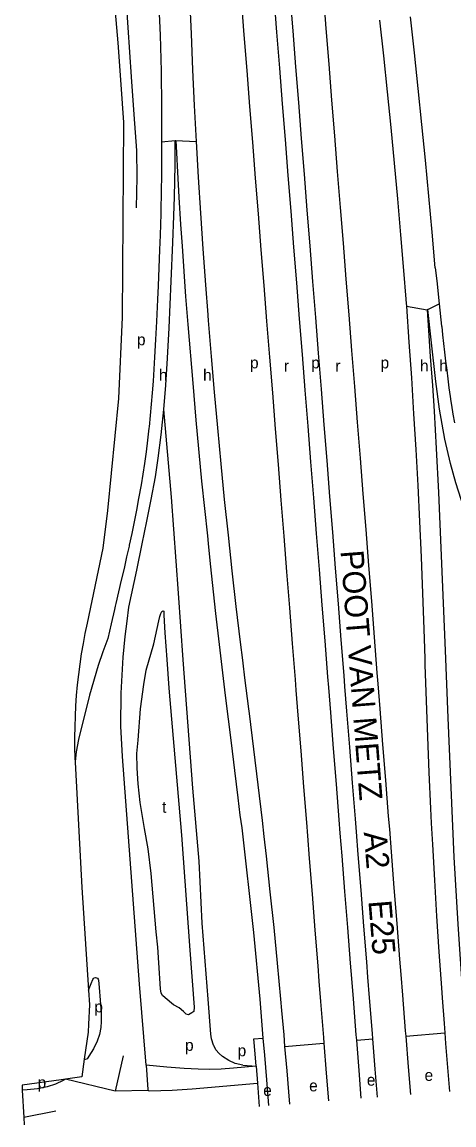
# Model space of a CAD drawing. Extents: x 157794 to 159375, y 380877 to 382306.
# Drawn here: x 157793.8 to 157944, y 380877 to 381260.8 of the extents above; entities that cross this region are included whole.
import ezdxf

# ---------------------------------------------------------------- set-up
doc = ezdxf.new("R2010")
doc.units = 0
for name, color, linetype in [('BLT_Basislijn', 7, 'Continuous'), ('BLT_Centroide', 7, 'Continuous'), ('BLT_Gemeentegrens', 7, 'Continuous'), ('BLT_Straatnaam_hoofdweg', 7, 'Continuous'), ('BLT_Vlakafsluiter', 7, 'Continuous')]:
    doc.layers.add(name, color=color, linetype=linetype)

msp = doc.modelspace()

# ---------------------------------------------------------------- linework, layer by layer
at = {"layer": 'BLT_Basislijn'}
for p, q in [((157847.06, 381219.6), (157847.27, 381219.6)), ((157845.78, 381095.42), (157843.13, 381125.9)), ((157910.17, 380906.42), (157915.75, 380906.88)), ((157927.21, 380907.85), (157940.76, 380908.99)), ((157885.1, 380904.31), (157898.71, 380905.45)), ((157828.9, 380900.99), (157826.11, 380888.76)), ((157870.61, 380897.76), (157875.17, 380897.39)), ((157875.17, 380897.39), (157875.62, 380891.48)), ((157875.62, 380891.48), (157876.23, 380883.41)), ((157805.55, 380881.8), (157794.37, 380879.52))]:
    msp.add_line(p, q, dxfattribs=at)
for points in [[(157838.3, 381404.1), (157838.34, 381403.5), (157838.4, 381401.23), (157838.41, 381400.88), (157838.57, 381393.52), (157838.8, 381381.04), (157838.98, 381368.57), (157839.09, 381356.1), (157839.15, 381343.62), (157839.16, 381340.46), (157839.15, 381331.16), (157839.14, 381328.66), (157839.56, 381318.71), (157840.04, 381306.27), (157840.46, 381293.82), (157840.62, 381288.51), (157840.84, 381281.32), (157840.89, 381279.75), (157841.27, 381268.78), (157841.76, 381256.24), (157842.11, 381243.7), (157842.3, 381231.14), (157842.32, 381219.08)], [(157825.06, 381390.44), (157823.42, 381383.18), (157823.24, 381377.09), (157823.39, 381366.32), (157823.39, 381358.68), (157823.61, 381346.59), (157824.14, 381335.97), (157824.42, 381322.97), (157825.55, 381312.41), (157827.15, 381295.92), (157829.34, 381277.88), (157830.56, 381258.85), (157831.69, 381241.7), (157832.65, 381228.56), (157833.59, 381216.13), (157833.7, 381206.77), (157833.46, 381196.16)], [(157851.57, 381283.73), (157851.63, 381281.67), (157851.68, 381280.1), (157852.06, 381269.18), (157852.55, 381256.69), (157853.09, 381244.2), (157853.69, 381231.72), (157854.35, 381219.24)], [(157898.49, 381271.05), (157899.47, 381258.59), (157900.46, 381246.13), (157901.44, 381233.66), (157902.43, 381221.2), (157903.41, 381208.74), (157904.4, 381196.28), (157905.39, 381183.82), (157906.37, 381171.36), (157907.36, 381158.9), (157908.34, 381146.44), (157909.33, 381133.98), (157910.31, 381121.51), (157911.3, 381109.05), (157912.28, 381096.59), (157913.27, 381084.13), (157914.25, 381071.67), (157915.24, 381059.21), (157916.22, 381046.75), (157917.21, 381034.29), (157917.51, 381030.49), (157918.19, 381021.83), (157919.18, 381009.36), (157920.17, 380996.9), (157921.15, 380984.44), (157921.51, 380979.88), (157922.14, 380971.98), (157923.12, 380959.52), (157924.11, 380947.06), (157925.09, 380934.6), (157925.51, 380929.27), (157926.08, 380922.14), (157927.06, 380909.68), (157927.21, 380907.85)], [(157869.98, 381268.79), (157870.96, 381256.33), (157871.95, 381243.87), (157872.93, 381231.41), (157873.92, 381218.95), (157874.9, 381206.49), (157875.89, 381194.03), (157876.87, 381181.57), (157877.86, 381169.1), (157878.84, 381156.64), (157879.83, 381144.18), (157880.82, 381131.72), (157881.8, 381119.26), (157882.79, 381106.8), (157883.77, 381094.34), (157884.76, 381081.88), (157885.74, 381069.42), (157886.73, 381056.95), (157887.71, 381044.49), (157888.7, 381032.03), (157889, 381028.23), (157889.68, 381019.57), (157890.67, 381007.11), (157891.65, 380994.65), (157892.64, 380982.19), (157893, 380977.63), (157893.63, 380969.73), (157894.61, 380957.27), (157895.6, 380944.8), (157896.58, 380932.34), (157897, 380927.02), (157897.57, 380919.88), (157898.55, 380907.42), (157898.71, 380905.45)], [(157910.17, 380906.42), (157910.02, 380908.33), (157909.03, 380920.79), (157908.47, 380927.92), (157908.05, 380933.25), (157907.06, 380945.71), (157906.07, 380958.17), (157905.09, 380970.63), (157904.46, 380978.53), (157904.1, 380983.09), (157903.12, 380995.56), (157902.13, 381008.02), (157901.15, 381020.48), (157900.46, 381029.14), (157900.16, 381032.94), (157899.18, 381045.4), (157898.19, 381057.86), (157897.21, 381070.32), (157896.22, 381082.78), (157895.24, 381095.24), (157894.25, 381107.71), (157893.27, 381120.17), (157892.28, 381132.63), (157891.29, 381145.09), (157890.31, 381157.55), (157889.32, 381170.01), (157888.34, 381182.47), (157887.35, 381194.93), (157886.37, 381207.39), (157885.38, 381219.86), (157884.4, 381232.32), (157883.41, 381244.78), (157882.43, 381257.24), (157881.44, 381269.7)], [(157915.75, 380906.88), (157915.6, 380908.77), (157914.61, 380921.23), (157914.05, 380928.37), (157913.63, 380933.69), (157912.64, 380946.15), (157911.66, 380958.61), (157910.67, 380971.07), (157910.05, 380978.97), (157909.69, 380983.54), (157908.7, 380996), (157907.72, 381008.46), (157906.73, 381020.92), (157906.05, 381029.58), (157905.75, 381033.38), (157904.76, 381045.84), (157903.77, 381058.3), (157902.79, 381070.76), (157901.8, 381083.22), (157900.82, 381095.69), (157899.83, 381108.15), (157898.85, 381120.61), (157897.86, 381133.07), (157896.88, 381145.53), (157895.89, 381157.99), (157894.91, 381170.45), (157893.92, 381182.91), (157892.94, 381195.37), (157891.95, 381207.84), (157890.96, 381220.3), (157889.98, 381232.76), (157888.99, 381245.22), (157888.01, 381257.68), (157887.02, 381270.14)], [(157937.46, 381175.29), (157936.38, 381187.7), (157935.23, 381200.19), (157934.03, 381212.68), (157932.77, 381225.17), (157931.51, 381237.65), (157930.2, 381250.13), (157928.83, 381262.6)], [(157918.1, 381261.4), (157919.46, 381248.98), (157920.77, 381236.55), (157922.02, 381224.11), (157923.22, 381211.67), (157924.35, 381199.22), (157925.43, 381186.77), (157926.45, 381174.32), (157927.22, 381164.35), (157927.24, 381164.08), (157927.41, 381161.86)], [(157842.32, 381219.08), (157842.26, 381206.53), (157842.21, 381202.85), (157842.03, 381194.03)], [(157843.13, 381125.9), (157843.81, 381134.42), (157844.35, 381143.77), (157844.99, 381154.35), (157845.62, 381170.58), (157846.22, 381184.02), (157846.59, 381193.38), (157846.79, 381199.99), (157847, 381210.94), (157847.06, 381219.6)], [(157847.27, 381219.6), (157847.49, 381215.33), (157847.82, 381208.58), (157848.36, 381199.89), (157848.94, 381190.37), (157849.42, 381182.8), (157850.64, 381165.33), (157851.38, 381155.49), (157853.12, 381135.14), (157854.18, 381122.23), (157856.2, 381100.97), (157858.25, 381082.03), (157858.48, 381079.28), (157859.22, 381072.24), (157861.1, 381054.94), (157862.33, 381044.14), (157864.45, 381026.42), (157866.46, 381009.89), (157867.64, 381000.35), (157868.84, 380990.8), (157869.49, 380984.81), (157870.22, 380980.34), (157874.22, 380943.96), (157876.44, 380920.72), (157877.57, 380907.2)], [(157854.35, 381219.24), (157855.07, 381206.76), (157855.84, 381194.29), (157856.68, 381181.82), (157857.57, 381169.35), (157858.36, 381158.88), (157858.37, 381158.68), (157858.51, 381156.89), (157859.52, 381144.43), (157860.58, 381131.98), (157861.7, 381119.53), (157862.88, 381107.09), (157864.12, 381094.65), (157865.41, 381082.22), (157866.76, 381069.8), (157868.17, 381057.38), (157869.64, 381044.97), (157870.39, 381038.75)], [(157842.03, 381194.03), (157841.81, 381186.67), (157841.63, 381181.53), (157841.09, 381169.04), (157840.88, 381164.24), (157840.53, 381156.56), (157840.23, 381150.34), (157839.89, 381144.12), (157839.64, 381139.98), (157839.36, 381135.85), (157839.05, 381131.73), (157838.73, 381127.79), (157838.36, 381123.86), (157837.96, 381119.94), (157837.9, 381119.4), (157837.42, 381115.31), (157836.9, 381111.22), (157836.32, 381107.14), (157835.76, 381103.45), (157835.16, 381099.77), (157834.31, 381094.94), (157833.55, 381090.88), (157832.75, 381086.83), (157831.91, 381082.77), (157831.05, 381078.72), (157830.98, 381078.4), (157830.15, 381074.68), (157829.24, 381070.63), (157828.31, 381066.58), (157827.37, 381062.53), (157826.42, 381058.48), (157826.18, 381057.47), (157825.92, 381056.35), (157824.74, 381051.32), (157823.59, 381046.25), (157821.88, 381041.64), (157820.26, 381036.82), (157817.27, 381026.54), (157813.41, 381011.07), (157812.65, 381006.8), (157812.32, 381004.6), (157812.24, 381003.17)], [(157937.46, 381175.29), (157937.96, 381170.68), (157938.83, 381162.75)], [(157927.41, 381161.86), (157928.32, 381149.39), (157929.16, 381136.92), (157929.95, 381124.45), (157930.69, 381111.97), (157931.36, 381099.49), (157931.98, 381087.01), (157932.53, 381074.53), (157933.03, 381062.04), (157933.48, 381049.55), (157933.69, 381042.72), (157933.8, 381039.18), (157933.86, 381037.05), (157934.27, 381024.56), (157934.73, 381012.07), (157935.25, 380999.57), (157935.83, 380987.09), (157936.08, 380981.95), (157936.47, 380974.6), (157937.16, 380962.12), (157937.91, 380949.64), (157938.72, 380937.16), (157939.59, 380924.69), (157939.84, 380921.25), (157940.51, 380912.22), (157940.76, 380908.99)], [(157934.94, 381160.71), (157934.65, 381160.68)], [(157934.65, 381160.68), (157935.7, 381144.42), (157936.49, 381134.3), (157937.03, 381125.41), (157937.84, 381112.36), (157938.63, 381097.02), (157939.91, 381066.83), (157940.97, 381042.02), (157941.87, 381018.61), (157942.89, 380994.44), (157943.91, 380970.19), (157945.28, 380946.87), (157946.92, 380922.55), (157947.64, 380912.88)], [(157955.82, 381069.77), (157951.64, 381079.87), (157948.21, 381089.13), (157944.6, 381100.37), (157942.75, 381107.14), (157940.84, 381115.66), (157938.98, 381126.08), (157937.64, 381135.68), (157936.03, 381150.24), (157934.94, 381160.71)], [(157938.83, 381162.75), (157939.69, 381154.98), (157939.71, 381154.78), (157940.02, 381151.96), (157940.02, 381151.93), (157940.36, 381148.89), (157940.7, 381145.85), (157941.06, 381142.76), (157941.44, 381139.68), (157941.82, 381136.6), (157942.23, 381133.53), (157942.66, 381130.46), (157942.91, 381128.77), (157943.12, 381127.41), (157943.6, 381124.36), (157944.12, 381121.32)], [(157836.89, 380897.78), (157834.67, 380925.92), (157828.71, 381005.16), (157828.15, 381015.78), (157828.23, 381027.2), (157828.97, 381039.75), (157829.7, 381046.91), (157830.33, 381052.34), (157830.95, 381057.1), (157833.74, 381069.99), (157835.6, 381079.14), (157837.23, 381087.08), (157838.72, 381094.64), (157840.22, 381102.57), (157841.17, 381108.97), (157842.17, 381117.12), (157843.13, 381125.9)], [(157860.41, 380904.67), (157859.66, 380906.89), (157859.42, 380908.58), (157858.49, 380920.7), (157856.44, 380947.23), (157855.32, 380968.74), (157853.2, 380994.21), (157849.81, 381038.87), (157848.18, 381062.01), (157845.78, 381095.42)], [(157870.39, 381038.75), (157870.52, 381037.69), (157871.16, 381032.56), (157872.53, 381021.79), (157872.74, 381020.16), (157874.31, 381007.76), (157875.82, 380995.35), (157877.27, 380982.93), (157877.9, 380977.32), (157878.66, 380970.51), (157880, 380958.08), (157881.28, 380945.64), (157882.5, 380933.2), (157883.66, 380920.75), (157884.02, 380916.8), (157884.77, 380908.3), (157885.1, 380904.31)], [(157816.92, 380923.84), (157817.85, 380926.2), (157818.42, 380927.61), (157818.6, 380927.9), (157818.89, 380928.14), (157819.27, 380928.26), (157819.69, 380928.18), (157819.98, 380928), (157820.24, 380927.67), (157820.37, 380927.34), (157820.58, 380924.84), (157821.29, 380915.92), (157821.3, 380912.91), (157821.13, 380910.91), (157820.68, 380908.46), (157819.92, 380906.1), (157818.62, 380903.48), (157817.84, 380902.17), (157816.39, 380900.01), (157815.9, 380899.78), (157815.42, 380899.83)], [(157874.81, 380901.68), (157874.37, 380906.93), (157877.57, 380907.2)], [(157877.57, 380907.2), (157878.07, 380901.28)], [(157911.76, 380886.22), (157911, 380895.87), (157910.17, 380906.42)], [(157917.35, 380886.66), (157916.58, 380896.31), (157915.75, 380906.88)], [(157927.21, 380907.85), (157928.05, 380897.21), (157928.81, 380887.56)], [(157940.76, 380908.99), (157941.05, 380905.35), (157941.49, 380899.76), (157942.37, 380888.63)], [(157870.61, 380897.76), (157867.86, 380898.34), (157865.71, 380899.38), (157863.45, 380900.79), (157862.3, 380901.82), (157861.21, 380903.08), (157860.44, 380904.58), (157860.41, 380904.67)], [(157885.1, 380904.31), (157885.82, 380895.84), (157886.41, 380888.49), (157886.74, 380884.24)], [(157898.71, 380905.45), (157899.54, 380894.96), (157900.3, 380885.31)], [(157875.17, 380897.39), (157874.81, 380901.68)], [(157878.07, 380901.28), (157878.78, 380892.68), (157879.53, 380883.67)], [(157875.17, 380897.39), (157867.34, 380896.67), (157863.08, 380896.38), (157858.98, 380896.24), (157855.02, 380896.31), (157850.19, 380896.59), (157844.16, 380897.11), (157836.89, 380897.78)], [(157808.91, 380892.91), (157808.14, 380892.44), (157805.44, 380891.12), (157802.51, 380890.24), (157799.11, 380889.55), (157795.58, 380889.21), (157793.88, 380889.11)], [(157837.68, 380888.92), (157838.09, 380888.77), (157845.98, 380889.02), (157852.9, 380889.55), (157875.62, 380891.48)]]:
    msp.add_lwpolyline(points, dxfattribs=at)
msp.add_lwpolyline([(157841.33, 381052.38), (157841.67, 381053.87), (157842, 381054.99), (157842.37, 381055.69), (157842.76, 381055.93), (157843.07, 381055.77), (157843.1, 381054.33), (157843.38, 381048.25), (157844.1, 381038.97), (157844.85, 381028.97), (157849.21, 380977.76), (157852.14, 380937.83), (157853.67, 380917.9), (157853.47, 380916.45), (157852.78, 380915.93), (157851.63, 380915.3), (157850.87, 380915.46), (157849.88, 380916.45), (157848.38, 380917.68), (157846.4, 380918.78), (157843.53, 380921.18), (157842.64, 380922.06), (157842.2, 380922.78), (157841.94, 380924.28), (157841.39, 380933.36), (157840.97, 380938.81), (157840.39, 380944.19), (157838.73, 380964.42), (157837.67, 380973.04), (157836.34, 380980.07), (157834.9, 380989.22), (157834.2, 380995.67), (157833.86, 381001.12), (157833.74, 381006.22), (157834.13, 381010.88), (157835.02, 381021.77), (157836.1, 381030.24), (157836.98, 381035.25), (157839.57, 381044.42)], close=True, dxfattribs=at)
at = {"layer": 'BLT_Gemeentegrens'}
for p, q in [((157793.88, 380889.11), (157794.37, 380879.52)), ((157794.37, 380879.52), (157794.5, 380876.96))]:
    msp.add_line(p, q, dxfattribs=at)
for points in [[(157821.16, 381321.86), (157827.04, 381253.5), (157828.11, 381239.04), (157829.09, 381225.83), (157828.63, 381158.04), (157827.3, 381129.73), (157823.48, 381090.84), (157821.93, 381077.7), (157816.41, 381051.59), (157815.66, 381048.03), (157814.99, 381044.46), (157814.38, 381040.88), (157813.84, 381037.28), (157813.38, 381033.68), (157812.98, 381030.07), (157812.66, 381026.45), (157812.4, 381022.82), (157812.21, 381019.19), (157812.1, 381015.56), (157812.05, 381011.92), (157812.07, 381008.29), (157812.17, 381004.65), (157812.24, 381003.17)], [(157812.24, 381003.17), (157812.34, 381001.02), (157814.61, 380959.61), (157816.92, 380923.84)], [(157816.92, 380923.84), (157817.25, 380918.7), (157816.94, 380911.98), (157816.81, 380909.25), (157815.42, 380899.83)], [(157815.42, 380899.83), (157814.52, 380893.68), (157808.91, 380892.91)], [(157808.91, 380892.91), (157807.4, 380892.7), (157793.8, 380890.84), (157793.88, 380889.11)]]:
    msp.add_lwpolyline(points, dxfattribs=at)
at = {"layer": 'BLT_Vlakafsluiter'}
for p, q in [((157842.32, 381219.08), (157847.06, 381219.6)), ((157847.27, 381219.6), (157854.35, 381219.24)), ((157927.41, 381161.86), (157934.65, 381160.68)), ((157934.94, 381160.71), (157938.83, 381162.75)), ((157826.11, 380888.76), (157808.91, 380892.91)), ((157837.68, 380888.92), (157826.11, 380888.76))]:
    msp.add_line(p, q, dxfattribs=at)
msp.add_lwpolyline([(157836.89, 380897.78), (157837.5, 380889.26), (157837.68, 380888.92)], dxfattribs=at)

# ---------------------------------------------------------------- texts
at = {"layer": 'BLT_Centroide'}
for s, p in [('p', (157833.76, 381148.29)), ('h', (157841.37, 381135.93)), ('h', (157856.74, 381135.93)), ('p', (157873.06, 381140.26)), ('r', (157884.83, 381139.15)), ('p', (157894.34, 381140.26)), ('r', (157902.73, 381139.15)), ('p', (157918.45, 381140.26)), ('h', (157932.18, 381139.19)), ('h', (157938.85, 381139.19)), ('t', (157842.46, 380985.59)), ('p', (157818.94, 380916.14)), ('p', (157850.47, 380902.75)), ('p', (157868.77, 380900.86)), ('e', (157933.76, 380892.28)), ('p', (157799.21, 380889.73)), ('e', (157893.62, 380888.65)), ('e', (157913.68, 380890.62)), ('e', (157877.65, 380887.04))]:
    msp.add_text(s, height=4, dxfattribs=at).set_placement(p)
at = {"layer": 'BLT_Straatnaam_hoofdweg'}
for s, height, rotation, p in [('POOT VAN METZ', 7.9999, 274.3677, (157904.52, 381076.73)), ('A2', 8, 274.6416, (157912.59, 380978.8)), ('E25', 8, 274.6416, (157914.21, 380954.89))]:
    msp.add_text(s, height=height, rotation=rotation, dxfattribs=at).set_placement(p)

doc.saveas('drawing.dxf')
